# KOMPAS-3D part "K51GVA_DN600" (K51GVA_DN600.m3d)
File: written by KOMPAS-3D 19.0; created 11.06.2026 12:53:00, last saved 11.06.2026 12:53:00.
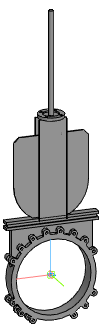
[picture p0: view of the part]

Document properties: Автор: Энергия; Полное имя файла: Z:\3.Личные\kachalov\001_3d для проектировщиков\2.6 Тип_K51GVA. Задвижка\_stp\_stp_K51GVA_DN50-DN1000_с фланцем\K51GVA_DN600.m3d

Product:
- Part/product: K51GVA_DN600

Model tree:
1. Операция без истории:1  (labels: K51GVA_DN600)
